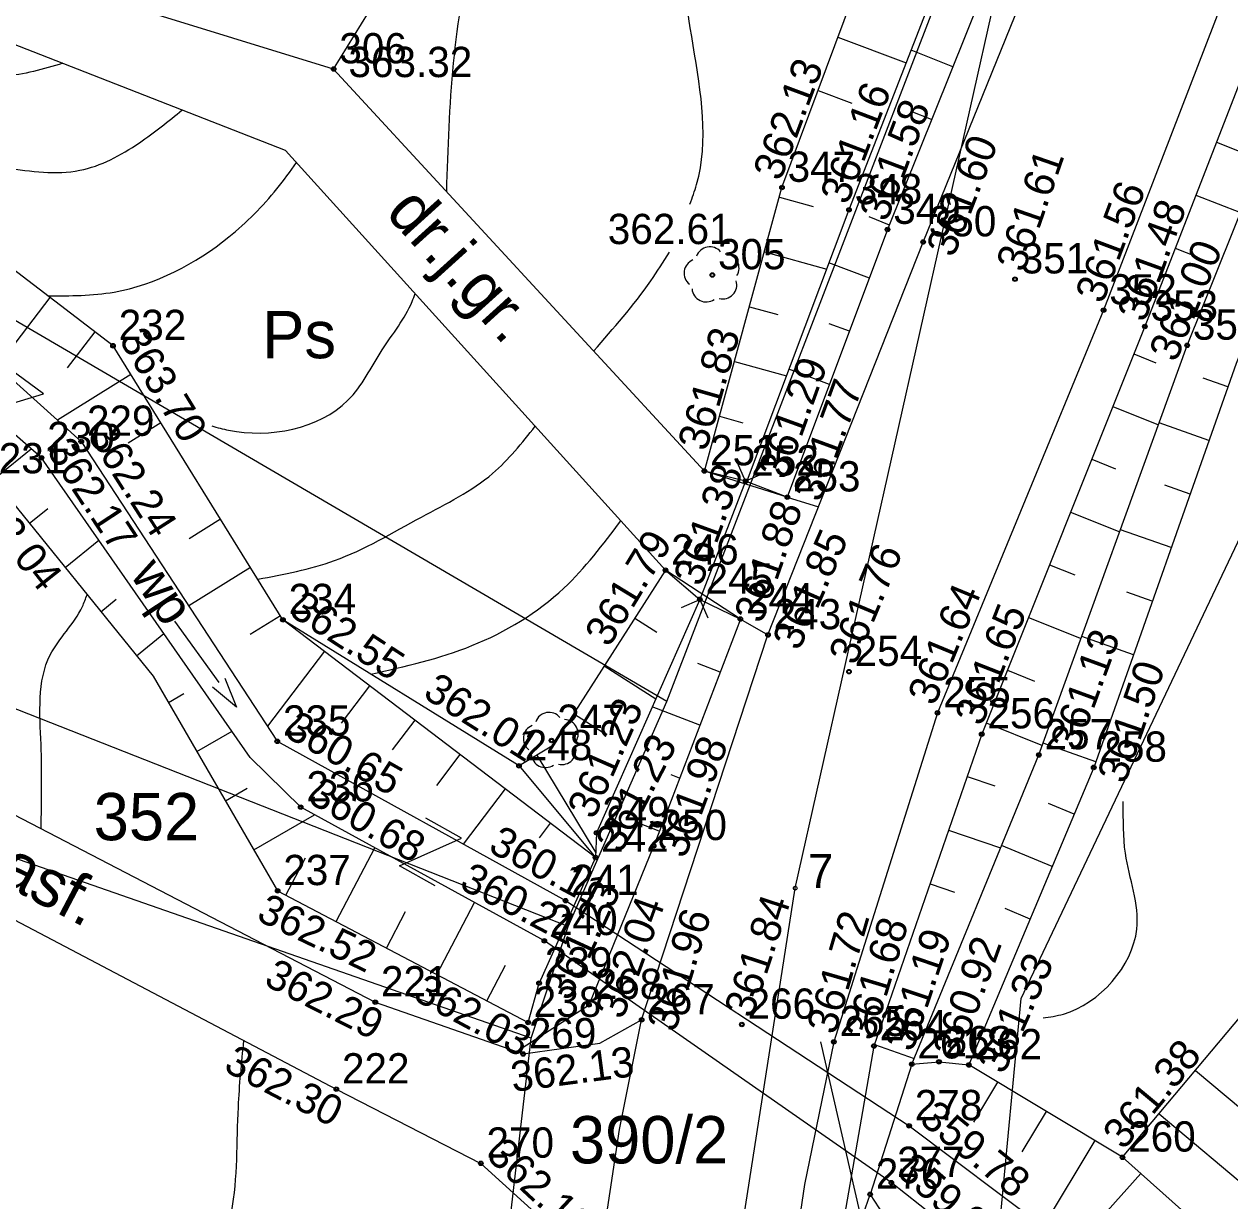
# Model space of a CAD drawing. Extents: x 4635329 to 4651863, y 5356628 to 5367582.
# Drawn here: x 4651713.58 to 4651745.45, y 5357153.92 to 5357185.01 of the extents above; entities that cross this region are included whole.
import ezdxf

# ---------------------------------------------------------------- set-up
doc = ezdxf.new("R2010")
doc.units = 0
for name, color, linetype in [('Level 12', 7, 'Continuous'), ('Level 2', 7, 'Continuous'), ('Level 20', 7, 'Continuous'), ('Level 21', 7, 'Continuous'), ('Level 22', 7, 'Continuous'), ('Level 24', 7, 'Continuous'), ('Level 29', 7, 'Continuous'), ('Level 4', 7, 'Continuous'), ('Level 44', 7, 'Continuous'), ('Level 45', 7, 'Continuous'), ('Level 46', 7, 'Continuous'), ('Level 48', 7, 'Continuous'), ('Level 5', 7, 'Continuous'), ('Level 50', 7, 'Continuous'), ('Level 51', 7, 'Continuous'), ('Level 53', 7, 'Continuous'), ('Level 55', 7, 'Continuous'), ('Level 62', 7, 'Continuous'), ('Level 63', 7, 'Continuous')]:
    doc.layers.add(name, color=color, linetype=linetype)

msp = doc.modelspace()

# ---------------------------------------------------------------- linework, layer by layer
at = {"layer": 'Level 2'}
msp.add_line((4651752.271, 5357081.395), (4651734.633, 5357158.117), dxfattribs=at)
at = {"layer": 'Level 20'}
for points in [[(4651729.82, 5357135.56), (4651729.11, 5357142.98), (4651728.67, 5357151.53), (4651729.317, 5357155.805), (4651729.9, 5357158.7), (4651733.24, 5357168.87), (4651737.34, 5357179.25), (4651742.57, 5357192.12), (4651752.49, 5357216.86)], [(4651756.54, 5357214.25), (4651747.08, 5357190.33), (4651742.11, 5357177.45), (4651737.72, 5357166.81), (4651734.98, 5357158.12), (4651734.207, 5357154.352), (4651733.71, 5357151.02), (4651733.66, 5357143.55), (4651734.7, 5357135.16)], [(4651721.76, 5357183.82), (4651713.66, 5357186.32)], [(4651720.492, 5357181.672), (4651713.051, 5357184.577)], [(4651733.75, 5357172.51), (4651731.56, 5357173.2), (4651721.76, 5357183.82)], [(4651732.51, 5357169.29), (4651730.53, 5357170.58), (4651720.492, 5357181.672)], [(4651733.75, 5357172.51), (4651734.577, 5357172.254)], [(4651732.51, 5357169.29), (4651733.24, 5357168.87)], [(4651704.65, 5357168.62), (4651722.86, 5357159.17), (4651726.77, 5357157.8), (4651728.792, 5357158.081), (4651729.9, 5357158.7)], [(4651703.46, 5357166.53), (4651721.83, 5357156.87), (4651725.65, 5357154.91), (4651727.94, 5357152.83), (4651728.67, 5357151.53)]]:
    msp.add_lwpolyline(points, dxfattribs=at)
at = {"layer": 'Level 22'}
for points in [[(4651727.89, 5357161.85), (4651736.97, 5357155.9)], [(4651736.5, 5357154.4), (4651727.33, 5357160.79)]]:
    msp.add_lwpolyline(points, dxfattribs=at)
at = {"layer": 'Level 24'}
for p, q in [((4651732.65, 5357172.93), (4651732.436, 5357173.415)), ((4651732.65, 5357172.93), (4651731.44, 5357169.81)), ((4651733.135, 5357173.144), (4651732.65, 5357172.93)), ((4651730.955, 5357169.596), (4651731.44, 5357169.81)), ((4651731.44, 5357169.81), (4651731.654, 5357169.325))]:
    msp.add_line(p, q, dxfattribs=at)
at = {"layer": 'Level 29'}
for p, q in [((4651728.68, 5357162.99), (4651727.19, 5357159.67)), ((4651737.04, 5357157.53), (4651735.94, 5357154.09))]:
    msp.add_line(p, q, dxfattribs=at)
at = {"layer": 'Level 4'}
for p, q in [((4651730.567, 5357167.111), (4651747.646, 5357211.452)), ((4651733.96, 5357162.18), (4651745.05, 5357211.61)), ((4651730.567, 5357167.111), (4651708.252, 5357180.152)), ((4651739.93, 5357159.265), (4651748.54, 5357177.401)), ((4651727.96, 5357161.166), (4651705.281, 5357170.083)), ((4651727.96, 5357161.166), (4651730.567, 5357167.111)), ((4651726.979, 5357158.218), (4651703.522, 5357166.383)), ((4651729.077, 5357130.935), (4651733.96, 5357162.18)), ((4651726.979, 5357158.218), (4651727.96, 5357161.166)), ((4651738.202, 5357141.009), (4651739.93, 5357159.265)), ((4651724.857, 5357139.906), (4651726.979, 5357158.218))]:
    msp.add_line(p, q, dxfattribs=at)
at = {"layer": 'Level 44'}
for centre in [(4651721.76, 5357183.82), (4651733.61, 5357180.69), (4651735.38, 5357180.1), (4651736.4, 5357179.58), (4651737.34, 5357179.25), (4651731.77, 5357178.38), (4651739.77, 5357178.27), (4651742.11, 5357177.45), (4651743.2, 5357177.02), (4651715.93, 5357176.51), (4651744.32, 5357176.52), (4651715.09, 5357173.98), (4651714.04, 5357173.55), (4651731.56, 5357173.2), (4651732.65, 5357172.93), (4651733.75, 5357172.51), (4651730.53, 5357170.58), (4651731.44, 5357169.81), (4651720.42, 5357169.27), (4651732.51, 5357169.29), (4651733.24, 5357168.87), (4651735.38, 5357167.9), (4651737.72, 5357166.81), (4651738.89, 5357166.25), (4651720.27, 5357166.06), (4651727.52, 5357166.08), (4651740.4, 5357165.7), (4651726.66, 5357165.41), (4651741.85, 5357165.37), (4651720.89, 5357164.32), (4651728.71, 5357163.64), (4651730.22, 5357163.3), (4651728.68, 5357162.99), (4651720.28, 5357162.11), (4651727.89, 5357161.85), (4651727.33, 5357160.79), (4651727.19, 5357159.67), (4651722.86, 5357159.17), (4651728.51, 5357159.1), (4651726.9, 5357158.63), (4651729.9, 5357158.7), (4651732.55, 5357158.58), (4651734.98, 5357158.12), (4651736.04, 5357158.01), (4651726.77, 5357157.8), (4651737.76, 5357157.59), (4651737.04, 5357157.53), (4651738.55, 5357157.51), (4651721.83, 5357156.87), (4651736.97, 5357155.9), (4651742.61, 5357155.07), (4651725.65, 5357154.91), (4651736.5, 5357154.4), (4651735.94, 5357154.09)]:
    msp.add_circle(centre, 0.04, dxfattribs=at)
at = {"layer": 'Level 46'}
for points in [[(4651731.177, 5357180.25), (4651731.354, 5357180.769), (4651731.233, 5357187.987), (4651733.476, 5357191.202), (4651734.689, 5357193.749), (4651735.719, 5357198.237), (4651736.69, 5357200.845), (4651736.715, 5357200.891)], [(4651724.748, 5357180.582), (4651725.533, 5357187.259), (4651726.691, 5357190.229)], [(4651714.604, 5357183.971), (4651713.048, 5357183.63), (4651710.805, 5357183.812), (4651708.867, 5357183.824)], [(4651709.956, 5357181.568), (4651713.109, 5357181.204), (4651715.049, 5357181.144), (4651716.625, 5357181.871), (4651717.759, 5357182.739)], [(4651714.207, 5357177.826), (4651715.958, 5357177.929), (4651718.99, 5357179.385), (4651720.263, 5357180.658), (4651720.783, 5357181.351)], [(4651728.633, 5357176.372), (4651730.141, 5357178.222), (4651730.638, 5357178.981)], [(4651718.541, 5357174.39), (4651718.985, 5357174.279), (4651722.138, 5357175.068), (4651723.047, 5357176.402), (4651723.835, 5357177.676), (4651723.917, 5357177.888)], [(4651719.756, 5357170.341), (4651721.779, 5357170.833), (4651724.083, 5357171.985), (4651725.963, 5357173.137), (4651727.089, 5357174.383)], [(4651722.744, 5357167.833), (4651725.417, 5357168.588), (4651727.843, 5357170.105), (4651729.351, 5357171.884)], [(4651714.027, 5357163.754), (4651714.027, 5357165.978), (4651714.27, 5357168.343), (4651715.119, 5357169.617), (4651715.244, 5357169.931)], [(4651740.511, 5357158.75), (4651741.048, 5357158.855), (4651742.988, 5357161.099), (4651742.685, 5357163.101), (4651742.625, 5357164.435), (4651742.624, 5357164.473)], [(4651699.387, 5357150.073), (4651701.719, 5357150.572), (4651704.872, 5357149.784), (4651707.903, 5357148.45), (4651710.995, 5357148.025), (4651714.33, 5357147.843), (4651719.06, 5357153.605), (4651719.242, 5357156.395), (4651719.388, 5357158.154)]]:
    msp.add_spline(points, degree=3, dxfattribs=at)
at = {"layer": 'Level 48'}
for p, q in [((4651735.089, 5357184.658), (4651736.893, 5357183.985)), ((4651738.124, 5357183.875), (4651737.022, 5357184.318)), ((4651734.565, 5357183.252), (4651735.457, 5357182.92)), ((4651737.565, 5357182.483), (4651737.022, 5357182.701)), ((4651745.091, 5357181.884), (4651745.69, 5357181.651)), ((4651733.54, 5357180.434), (4651734.431, 5357180.19)), ((4651744.548, 5357180.486), (4651745.73, 5357180.026)), ((4651736.448, 5357179.699), (4651735.918, 5357179.912)), ((4651733.144, 5357178.987), (4651734.791, 5357178.536)), ((4651744.004, 5357179.088), (4651744.587, 5357178.861)), ((4651735.919, 5357178.296), (4651734.851, 5357178.696)), ((4651714.258, 5357177.788), (4651712.873, 5357175.975)), ((4651732.748, 5357177.54), (4651733.504, 5357177.333)), ((4651735.392, 5357176.891), (4651734.857, 5357177.091)), ((4651715.45, 5357176.877), (4651714.721, 5357175.923)), ((4651732.352, 5357176.094), (4651733.73, 5357175.716)), ((4651742.91, 5357176.294), (4651743.49, 5357176.062)), ((4651716.402, 5357175.749), (4651714.461, 5357174.546)), ((4651734.866, 5357175.486), (4651733.794, 5357175.888)), ((4651745.392, 5357175.42), (4651744.74, 5357175.65)), ((4651742.352, 5357174.902), (4651743.559, 5357174.419)), ((4651717.193, 5357174.474), (4651716.33, 5357173.939)), ((4651731.956, 5357174.647), (4651732.577, 5357174.477)), ((4651744.893, 5357174.006), (4651743.577, 5357174.469)), ((4651712.77, 5357172.978), (4651713.768, 5357173.788)), ((4651741.795, 5357173.509), (4651742.421, 5357173.258)), ((4651744.395, 5357172.591), (4651743.73, 5357172.825)), ((4651713.716, 5357171.813), (4651714.206, 5357172.211)), ((4651718.774, 5357171.925), (4651717.942, 5357171.409)), ((4651741.238, 5357172.116), (4651742.536, 5357171.597)), ((4651743.896, 5357171.176), (4651742.555, 5357171.649)), ((4651714.661, 5357170.649), (4651715.556, 5357171.375)), ((4651719.564, 5357170.65), (4651717.931, 5357169.637)), ((4651740.68, 5357170.724), (4651741.353, 5357170.455)), ((4651715.607, 5357169.484), (4651716.011, 5357169.813)), ((4651743.397, 5357169.761), (4651742.721, 5357170)), ((4651720.355, 5357169.375), (4651719.553, 5357168.878)), ((4651729.721, 5357169.317), (4651730.306, 5357168.942)), ((4651740.123, 5357169.331), (4651741.514, 5357168.775)), ((4651716.552, 5357168.32), (4651717.276, 5357168.907)), ((4651742.899, 5357168.347), (4651741.533, 5357168.828)), ((4651721.516, 5357168.437), (4651720.01, 5357166.457)), ((4651731.974, 5357167.889), (4651731.382, 5357168.115)), ((4651728.913, 5357168.053), (4651730.276, 5357167.18)), ((4651739.566, 5357167.939), (4651740.284, 5357167.651)), ((4651722.71, 5357167.529), (4651721.956, 5357166.537)), ((4651717.394, 5357167.084), (4651717.804, 5357167.322)), ((4651731.439, 5357166.488), (4651730.183, 5357166.968)), ((4651723.904, 5357166.621), (4651723.303, 5357165.831)), ((4651728.104, 5357166.79), (4651728.883, 5357166.291)), ((4651739.008, 5357166.546), (4651740.492, 5357165.952)), ((4651718.147, 5357165.787), (4651719.075, 5357166.325)), ((4651741.902, 5357165.517), (4651740.511, 5357166.007)), ((4651725.098, 5357165.714), (4651724.476, 5357164.896)), ((4651727.132, 5357165.694), (4651728.686, 5357163.115)), ((4651730.903, 5357165.087), (4651730.682, 5357165.172)), ((4651738.504, 5357165.134), (4651739.232, 5357164.882)), ((4651718.9, 5357164.489), (4651719.472, 5357164.821)), ((4651726.292, 5357164.806), (4651725.182, 5357163.346)), ((4651741.33, 5357164.131), (4651740.658, 5357164.413)), ((4651719.652, 5357163.192), (4651721.254, 5357164.121)), ((4651727.486, 5357163.898), (4651727.192, 5357163.511)), ((4651730.367, 5357163.686), (4651729.802, 5357163.902)), ((4651738.014, 5357163.716), (4651739.388, 5357163.241)), ((4651721.829, 5357161.296), (4651722.853, 5357163.244)), ((4651740.749, 5357162.748), (4651739.416, 5357163.307)), ((4651720.501, 5357161.994), (4651721.019, 5357162.98)), ((4651737.523, 5357162.298), (4651738.17, 5357162.075)), ((4651724.484, 5357159.9), (4651725.484, 5357161.802)), ((4651723.156, 5357160.598), (4651723.662, 5357161.561)), ((4651740.168, 5357161.365), (4651739.507, 5357161.642)), ((4651725.812, 5357159.202), (4651726.306, 5357160.142)), ((4651736.052, 5357158.046), (4651737.103, 5357157.682)), ((4651744.54, 5357157.367), (4651754.746, 5357148.794)), ((4651739.305, 5357157.056), (4651738.67, 5357156)), ((4651740.591, 5357156.283), (4651739.95, 5357155.216)), ((4651743.575, 5357156.219), (4651748.854, 5357151.784)), ((4651741.877, 5357155.511), (4651740.515, 5357153.245)), ((4651743.091, 5357154.641), (4651742.202, 5357153.644)), ((4651734.78, 5357150.75), (4651735.94, 5357154.09)), ((4651735.94, 5357154.09), (4651738.79, 5357149.75))]:
    msp.add_line(p, q, dxfattribs=at)
for points in [[(4651731.56, 5357173.2), (4651733.61, 5357180.69), (4651738.3, 5357193.27), (4651741.38, 5357200.19), (4651749.11, 5357218.24)], [(4651750.3, 5357217.62), (4651740.18, 5357192.43), (4651735.38, 5357180.1), (4651732.665, 5357172.888)], [(4651751.52, 5357217.29), (4651741.35, 5357191.91), (4651736.4, 5357179.58), (4651733.75, 5357172.51)], [(4651757.59, 5357214.04), (4651748.24, 5357189.98), (4651743.2, 5357177.02), (4651738.89, 5357166.25), (4651736.04, 5357158.01)], [(4651737.04, 5357157.53), (4651740.4, 5357165.7), (4651744.32, 5357176.52), (4651749.53, 5357189.48), (4651758.92, 5357213.52)], [(4651760.39, 5357213.04), (4651750.91, 5357189.19), (4651745.61, 5357176.04), (4651741.85, 5357165.37), (4651738.55, 5357157.51)], [(4651742.61, 5357155.07), (4651748.7, 5357162.32), (4651754.89, 5357171.81), (4651763.11, 5357183.48), (4651765.69, 5357188.91), (4651773.53, 5357204.88)], [(4651721.76, 5357183.82), (4651726.38, 5357191.31), (4651734.72, 5357201.25), (4651741.322, 5357200.062)], [(4651728.68, 5357162.99), (4651720.42, 5357169.27), (4651715.93, 5357176.51), (4651710.17, 5357180.91)], [(4651707.12, 5357174.99), (4651712.76, 5357172.99), (4651716.99, 5357167.781), (4651720.28, 5357162.11), (4651726.9, 5357158.63)], [(4651733.75, 5357172.51), (4651732.65, 5357172.93), (4651731.56, 5357173.2)], [(4651730.53, 5357170.58), (4651727.573, 5357165.96), (4651726.66, 5357165.41), (4651720.42, 5357169.27)], [(4651730.53, 5357170.58), (4651731.44, 5357169.81), (4651732.51, 5357169.29)], [(4651731.44, 5357169.81), (4651728.71, 5357163.64), (4651728.68, 5357162.99)], [(4651732.51, 5357169.29), (4651730.22, 5357163.3)], [(4651726.66, 5357165.41), (4651728.68, 5357162.99)], [(4651726.623, 5357157.88), (4651728.51, 5357159.1), (4651730.22, 5357163.3)], [(4651726.9, 5357158.63), (4651727.19, 5357159.67)], [(4651736.04, 5357158.01), (4651734.78, 5357150.75)], [(4651737.04, 5357157.53), (4651737.76, 5357157.59), (4651738.55, 5357157.51)], [(4651753.78, 5357146.52), (4651752.29, 5357147.1), (4651746.47, 5357151.63), (4651742.61, 5357155.07), (4651738.55, 5357157.51)]]:
    msp.add_lwpolyline(points, dxfattribs=at)
at = {"layer": 'Level 50'}
for p, q in [((4651717.556, 5357169.235), (4651718.722, 5357167.61)), ((4651719.189, 5357166.961), (4651718.559, 5357167.494)), ((4651718.885, 5357167.727), (4651719.189, 5357166.961)), ((4651736.97, 5357155.9), (4651745.02, 5357149.87)), ((4651744.47, 5357148.14), (4651736.5, 5357154.4))]:
    msp.add_line(p, q, dxfattribs=at)
for points in [[(4651709.189, 5357179.27), (4651709.89, 5357178.66), (4651715.09, 5357173.98), (4651720.27, 5357166.06), (4651727.89, 5357161.85)], [(4651727.33, 5357160.79), (4651720.89, 5357164.32), (4651719.558, 5357165.632), (4651714.04, 5357173.55), (4651708.27, 5357178.59)]]:
    msp.add_lwpolyline(points, dxfattribs=at)
at = {"layer": 'Level 53'}
for p, q in [((4651714.095, 5357175.241), (4651713.223, 5357175.878)), ((4651712.375, 5357174.715), (4651714.095, 5357175.241)), ((4651725.14, 5357163.502), (4651724.196, 5357164.027)), ((4651723.498, 5357162.769), (4651725.14, 5357163.502)), ((4651724.441, 5357162.244), (4651723.498, 5357162.769))]:
    msp.add_line(p, q, dxfattribs=at)
at = {"layer": 'Level 55'}
for centre in [(4651731.77, 5357178.38), (4651727.52, 5357166.08)]:
    msp.add_circle(centre, 0.045, dxfattribs=at)
for centre, start, end in [((4651731.703, 5357178.749), 40.3488, 160.1306), ((4651731.399, 5357178.43), 112.4389, 232.0902), ((4651732.1, 5357178.558), 328.348, 88.132), ((4651731.607, 5357178.042), 184.3875, 304.0933), ((4651732.041, 5357178.121), 256.3906, 16.0419), ((4651727.453, 5357166.449), 40.3488, 160.1306), ((4651727.85, 5357166.258), 328.348, 88.132), ((4651727.149, 5357166.13), 112.4389, 232.0902), ((4651727.791, 5357165.821), 256.3906, 16.0419), ((4651727.357, 5357165.742), 184.3875, 304.0933)]:
    msp.add_arc(centre, 0.375, start, end, dxfattribs=at)
at = {"layer": 'Level 62'}
msp.add_circle((4651733.96, 5357162.18), 0.05, dxfattribs=at)
at = {"layer": 'Level 63'}
for centre in [(4651721.76, 5357183.82), (4651733.61, 5357180.69), (4651735.38, 5357180.1), (4651736.4, 5357179.58), (4651737.34, 5357179.25), (4651731.77, 5357178.38), (4651739.77, 5357178.27), (4651742.11, 5357177.45), (4651743.2, 5357177.02), (4651715.93, 5357176.51), (4651744.32, 5357176.52), (4651715.09, 5357173.98), (4651714.04, 5357173.55), (4651731.56, 5357173.2), (4651732.65, 5357172.93), (4651733.75, 5357172.51), (4651730.53, 5357170.58), (4651731.44, 5357169.81), (4651720.42, 5357169.27), (4651732.51, 5357169.29), (4651733.24, 5357168.87), (4651735.38, 5357167.9), (4651737.72, 5357166.81), (4651738.89, 5357166.25), (4651720.27, 5357166.06), (4651727.52, 5357166.08), (4651740.4, 5357165.7), (4651726.66, 5357165.41), (4651741.85, 5357165.37), (4651720.89, 5357164.32), (4651728.71, 5357163.64), (4651730.22, 5357163.3), (4651728.68, 5357162.99), (4651720.28, 5357162.11), (4651727.89, 5357161.85), (4651727.33, 5357160.79), (4651727.19, 5357159.67), (4651722.86, 5357159.17), (4651728.51, 5357159.1), (4651726.9, 5357158.63), (4651729.9, 5357158.7), (4651732.55, 5357158.58), (4651734.98, 5357158.12), (4651736.04, 5357158.01), (4651726.77, 5357157.8), (4651737.04, 5357157.53), (4651737.76, 5357157.59), (4651738.55, 5357157.51), (4651721.83, 5357156.87), (4651736.97, 5357155.9), (4651742.61, 5357155.07), (4651725.65, 5357154.91), (4651736.5, 5357154.4), (4651735.94, 5357154.09)]:
    msp.add_circle(centre, 0.06, dxfattribs=at)

# ---------------------------------------------------------------- texts
at = {"layer": 'Level 12'}
msp.add_text('Ps', height=1.25, dxfattribs=at).set_placement((4651719.873, 5357176.18))
at = {"layer": 'Level 21'}
for s, rotation, p in [('dr.j.gr.', 312.1444, (4651723.102, 5357180.002)), ('dr.j.asf. ', 332.262, (4651710.348, 5357163.676))]:
    msp.add_text(s, height=1.25, rotation=rotation, dxfattribs=at).set_placement(p)
at = {"layer": 'Level 45'}
for s, p in [('363.32', (4651722.152, 5357183.607)), ('362.61', (4651729.006, 5357179.195))]:
    msp.add_text(s, height=0.8, dxfattribs=at).set_placement(p)
for s, rotation, p in [('362.13', 69.5732, (4651733.572, 5357180.834)), ('361.16', 69.1455, (4651735.342, 5357180.206)), ('361.58', 69.2614, (4651736.379, 5357179.755)), ('361.60', 68.7202, (4651738.146, 5357178.814)), ('361.61', 70.856, (4651740.007, 5357178.422)), ('361.56', 69.4491, (4651742.087, 5357177.592)), ('361.48', 70.1398, (4651743.201, 5357177.103)), ('361.00', 67.7386, (4651744.026, 5357176.048)), ('363.70', 301.4673, (4651716.073, 5357176.669)), ('361.83', 73.9909, (4651731.608, 5357173.695)), ('361.29', 70.1209, (4651733.715, 5357172.938)), ('361.77', 69.8679, (4651734.627, 5357172.351)), ('362.24', 302.5528, (4651715.234, 5357174.147)), ('362.17', 303.2936, (4651714.156, 5357173.737)), ('361.38', 69.9704, (4651731.47, 5357170.12)), ('363.04', 308.461, (4651711.981, 5357172.525)), ('361.88', 70.5879, (4651733.078, 5357169.145)), ('361.85', 66.2686, (4651734.061, 5357168.423)), ('361.79', 58.7114, (4651729.037, 5357168.515)), ('361.76', 67.3506, (4651735.553, 5357168.037)), ('361.64', 67.5695, (4651737.642, 5357166.969)), ('362.55', 326.9076, (4651720.54, 5357169.421)), ('361.65', 68.6214, (4651738.895, 5357166.433)), ('361.13', 69.8793, (4651741.431, 5357165.751)), ('361.50', 71.0015, (4651742.68, 5357164.908)), ('362.01', 327.5579, (4651724.088, 5357167.243)), ('361.23', 66.2938, (4651728.642, 5357163.968)), ('360.65', 330.4953, (4651720.425, 5357166.209)), ('361.23', 62.6767, (4651729.353, 5357163.065)), ('361.98', 69.4106, (4651731.047, 5357162.935)), ('360.68', 329.8623, (4651721.043, 5357164.469)), ('360.11', 331.923, (4651725.814, 5357163.164)), ('360.21', 332.3832, (4651725.049, 5357162.189)), ('361.23', 65.3135, (4651728.005, 5357159.17)), ('362.52', 334.282, (4651719.687, 5357161.352)), ('362.04', 70.0091, (4651729.405, 5357158.684)), ('361.84', 71.8643, (4651732.826, 5357158.718)), ('361.96', 72.9616, (4651730.79, 5357158.351)), ('361.72', 73.8023, (4651735.019, 5357158.282)), ('361.68', 73.2125, (4651736.018, 5357158.12)), ('361.19', 71.4351, (4651737.059, 5357157.828)), ('360.92', 70.2724, (4651738.327, 5357157.635)), ('362.29', 332.9292, (4651719.885, 5357159.641)), ('361.33', 65.9132, (4651739.474, 5357157.235)), ('362.03', 331.6199, (4651723.822, 5357159.256)), ('362.30', 332.3867, (4651718.819, 5357157.372)), ('362.13', 7.473, (4651726.496, 5357156.793)), ('361.38', 50.2633, (4651742.641, 5357155.238)), ('359.78', 320.8665, (4651737.205, 5357156.014)), ('362.18', 316.9859, (4651725.766, 5357155.074)), ('359.92', 318.939, (4651736.594, 5357154.652))]:
    msp.add_text(s, height=0.8, rotation=rotation, dxfattribs=at).set_placement(p)
at = {"layer": 'Level 5'}
for s, p in [('352', (4651715.418, 5357163.445)), ('390/2', (4651728.005, 5357154.909))]:
    msp.add_text(s, height=1.25, dxfattribs=at).set_placement(p)
at = {"layer": 'Level 51'}
msp.add_text('wp', height=1, rotation=303.5081, dxfattribs=at).set_placement((4651716.361, 5357170.465))
at = {"layer": 'Level 62'}
msp.add_text(' 7', height=0.9, dxfattribs=at).set_placement((4651733.96, 5357162.18))
at = {"layer": 'Level 63'}
for s, p in [('306', (4651721.91, 5357183.97)), ('347', (4651733.76, 5357180.84)), ('348', (4651735.53, 5357180.25)), ('349', (4651736.55, 5357179.73)), ('350', (4651737.49, 5357179.4)), ('305', (4651731.92, 5357178.53)), ('351', (4651739.92, 5357178.42)), ('352', (4651742.26, 5357177.6)), ('353', (4651743.35, 5357177.17)), ('232', (4651716.08, 5357176.66)), ('354', (4651744.47, 5357176.67)), ('229', (4651715.24, 5357174.13)), ('230', (4651714.19, 5357173.7)), ('251', (4651731.71, 5357173.35)), ('231', (4651712.91, 5357173.14)), ('252', (4651732.8, 5357173.08)), ('253', (4651733.9, 5357172.66)), ('246', (4651730.68, 5357170.73)), ('245', (4651731.59, 5357169.96)), ('234', (4651720.57, 5357169.42)), ('244', (4651732.66, 5357169.44)), ('243', (4651733.39, 5357169.02)), ('254', (4651735.53, 5357168.05)), ('255', (4651737.87, 5357166.96)), ('256', (4651739.04, 5357166.4)), ('235', (4651720.42, 5357166.21)), ('247', (4651727.67, 5357166.23)), ('257', (4651740.55, 5357165.85)), ('248', (4651726.81, 5357165.56)), ('258', (4651742, 5357165.52)), ('236', (4651721.04, 5357164.47)), ('249', (4651728.86, 5357163.79)), ('250', (4651730.37, 5357163.45)), ('242', (4651728.83, 5357163.14)), ('237', (4651720.43, 5357162.26)), ('241', (4651728.04, 5357162)), ('240', (4651727.48, 5357160.94)), ('239', (4651727.34, 5357159.82)), ('221', (4651723.01, 5357159.32)), ('268', (4651728.66, 5357159.25)), ('238', (4651727.05, 5357158.78)), ('267', (4651730.05, 5357158.85)), ('266', (4651732.7, 5357158.73)), ('265', (4651735.13, 5357158.27)), ('264', (4651736.19, 5357158.16)), ('269', (4651726.92, 5357157.95)), ('263', (4651737.91, 5357157.74)), ('261', (4651737.19, 5357157.68)), ('262', (4651738.7, 5357157.66)), ('222', (4651721.98, 5357157.02)), ('278', (4651737.12, 5357156.05)), ('260', (4651742.76, 5357155.22)), ('270', (4651725.8, 5357155.06)), ('277', (4651736.65, 5357154.55)), ('276', (4651736.09, 5357154.24))]:
    msp.add_text(s, height=0.8, dxfattribs=at).set_placement(p)

doc.saveas('drawing.dxf')
